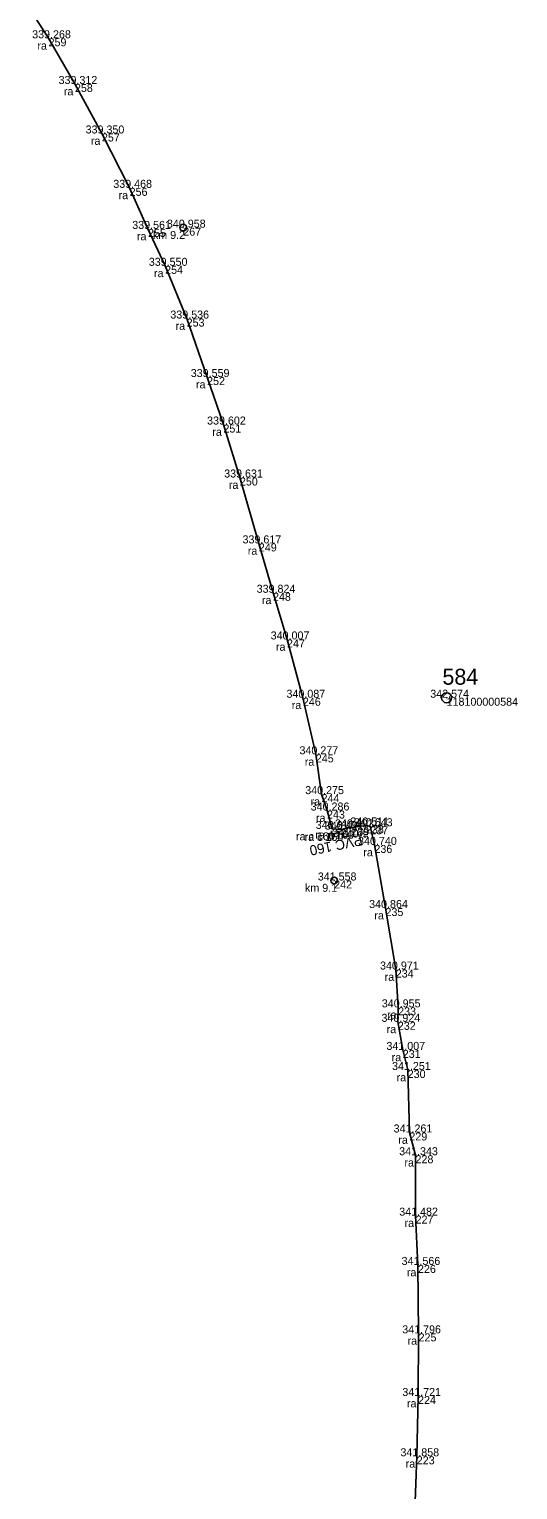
# Model space of a CAD drawing. Extents: x -727171 to -722443, y -945718 to -941834.
# Drawn here: x -725842.7 to -725769.5, y -942575.6 to -942356.6 of the extents above; entities that cross this region are included whole.
import ezdxf

# ---------------------------------------------------------------- set-up
doc = ezdxf.new("R2010")
doc.units = 0
for name, color, linetype in [('Vrstva 28', 7, 'Continuous'), ('Vrstva 35', 7, 'Continuous'), ('Vrstva 60', 7, 'Continuous'), ('Vrstva 61', 7, 'Continuous'), ('Vrstva 62', 7, 'Continuous'), ('Vrstva 63', 7, 'Continuous'), ('Vrstva 7', 7, 'Continuous')]:
    doc.layers.add(name, color=color, linetype=linetype)

msp = doc.modelspace()

# ---------------------------------------------------------------- linework, layer by layer
at = {"layer": 'Vrstva 28'}
msp.add_lwpolyline([(-725784.99, -942580.16), (-725784.63, -942570.61), (-725784.44, -942561.57), (-725784.36, -942552.18), (-725784.45, -942541.92), (-725784.81, -942534.53), (-725784.82, -942525.47), (-725785.74, -942522.06), (-725785.99, -942512.69), (-725786.73, -942509.68), (-725787.47, -942505.47), (-725787.42, -942503.3), (-725787.78, -942497.63), (-725789.32, -942488.41), (-725790.98, -942478.95), (-725791.61, -942476.15), (-725792.24, -942476.03), (-725794.44, -942476.32), (-725796.04, -942476.65), (-725797.33, -942476.55), (-725798.08, -942473.79), (-725798.9, -942471.33), (-725799.76, -942465.36), (-725801.7, -942456.88), (-725804.08, -942448.14), (-725806.18, -942441.14), (-725808.3, -942433.74), (-725811.14, -942423.86), (-725813.61, -942415.92), (-725816.06, -942408.8), (-725819.12, -942400.03), (-725822.35, -942392.12), (-725824.92, -942386.59), (-725827.67, -942380.43), (-725831.82, -942372.28), (-725835.87, -942364.86), (-725839.82, -942358.01), (-725842.72, -942353.5)], dxfattribs=at)
at = {"layer": 'Vrstva 35'}
msp.add_lwpolyline([(-725792.24, -942476.03), (-725794.44, -942476.32), (-725796.04, -942476.65), (-725797.33, -942476.55)], dxfattribs=at)
at = {"layer": 'Vrstva 60'}
for p, q in [((-725839.82, -942358.01), (-725839.82, -942358.01)), ((-725835.87, -942364.86), (-725835.87, -942364.86)), ((-725831.82, -942372.28), (-725831.82, -942372.28)), ((-725827.67, -942380.43), (-725827.67, -942380.43)), ((-725824.92, -942386.59), (-725824.92, -942386.59)), ((-725819.63, -942386.4), (-725819.63, -942386.4)), ((-725822.35, -942392.12), (-725822.35, -942392.12)), ((-725819.12, -942400.03), (-725819.12, -942400.03)), ((-725816.06, -942408.8), (-725816.06, -942408.8)), ((-725813.61, -942415.92), (-725813.61, -942415.92)), ((-725811.14, -942423.86), (-725811.14, -942423.86)), ((-725808.3, -942433.74), (-725808.3, -942433.74)), ((-725806.18, -942441.14), (-725806.18, -942441.14)), ((-725804.08, -942448.14), (-725804.08, -942448.14)), ((-725801.7, -942456.88), (-725801.7, -942456.88)), ((-725780.16, -942456.88), (-725780.16, -942456.88)), ((-725799.76, -942465.36), (-725799.76, -942465.36)), ((-725798.9, -942471.33), (-725798.9, -942471.33)), ((-725798.08, -942473.79), (-725798.08, -942473.79)), ((-725797.33, -942476.55), (-725797.33, -942476.55)), ((-725796.04, -942476.65), (-725796.04, -942476.65)), ((-725794.44, -942476.32), (-725794.44, -942476.32)), ((-725792.24, -942476.03), (-725792.24, -942476.03)), ((-725791.61, -942476.15), (-725791.61, -942476.15)), ((-725790.98, -942478.95), (-725790.98, -942478.95)), ((-725797.01, -942484.28), (-725797.01, -942484.28)), ((-725789.32, -942488.41), (-725789.32, -942488.41)), ((-725787.78, -942497.63), (-725787.78, -942497.63)), ((-725787.42, -942503.3), (-725787.42, -942503.3)), ((-725787.47, -942505.47), (-725787.47, -942505.47)), ((-725786.73, -942509.68), (-725786.73, -942509.68)), ((-725785.99, -942512.69), (-725785.99, -942512.69)), ((-725785.74, -942522.06), (-725785.74, -942522.06)), ((-725784.82, -942525.47), (-725784.82, -942525.47)), ((-725784.81, -942534.53), (-725784.81, -942534.53)), ((-725784.45, -942541.92), (-725784.45, -942541.92)), ((-725784.36, -942552.18), (-725784.36, -942552.18)), ((-725784.44, -942561.57), (-725784.44, -942561.57)), ((-725784.63, -942570.61), (-725784.63, -942570.61))]:
    msp.add_line(p, q, dxfattribs=at)
at = {"layer": 'Vrstva 63'}
msp.add_line((-725780.2, -942456.88), (-725780.1, -942456.88), dxfattribs=at)
msp.add_circle((-725780.16, -942456.88), 0.756, dxfattribs=at)
at = {"layer": 'Vrstva 7'}
for p, q in [((-725819.68, -942386.4), (-725819.58, -942386.4)), ((-725797.06, -942484.28), (-725796.96, -942484.28))]:
    msp.add_line(p, q, dxfattribs=at)
for centre in [(-725819.63, -942386.4), (-725797.01, -942484.28)]:
    msp.add_circle(centre, 0.5, dxfattribs=at)

# ---------------------------------------------------------------- texts
at = {"layer": 'Vrstva 35'}
msp.add_text('PVC 160', height=1.5, rotation=191.4815, dxfattribs=at).set_placement((-725792.94, -942477.5))
at = {"layer": 'Vrstva 60'}
for s, p in [('259', (-725839.82, -942359.21)), ('258', (-725835.87, -942366.06)), ('257', (-725831.82, -942373.48)), ('256', (-725827.67, -942381.63)), ('255', (-725824.92, -942387.79)), ('267', (-725819.63, -942387.6)), ('254', (-725822.35, -942393.32)), ('253', (-725819.12, -942401.23)), ('252', (-725816.06, -942410)), ('251', (-725813.61, -942417.12)), ('250', (-725811.14, -942425.06)), ('249', (-725808.3, -942434.94)), ('248', (-725806.18, -942442.34)), ('247', (-725804.08, -942449.34)), ('246', (-725801.7, -942458.08)), ('118100000584', (-725780.16, -942458.08)), ('245', (-725799.76, -942466.57)), ('244', (-725798.9, -942472.53)), ('243', (-725798.08, -942474.99)), ('241', (-725797.33, -942477.75)), ('240', (-725796.04, -942477.85)), ('239', (-725794.44, -942477.52)), ('238', (-725792.24, -942477.23)), ('237', (-725791.61, -942477.35)), ('236', (-725790.98, -942480.15)), ('242', (-725797.01, -942485.48)), ('235', (-725789.32, -942489.61)), ('234', (-725787.78, -942498.83)), ('233', (-725787.42, -942504.5)), ('232', (-725787.47, -942506.67)), ('231', (-725786.73, -942510.88)), ('230', (-725785.99, -942513.89)), ('229', (-725785.74, -942523.26)), ('228', (-725784.82, -942526.67)), ('227', (-725784.81, -942535.72)), ('226', (-725784.45, -942543.12)), ('225', (-725784.36, -942553.38)), ('224', (-725784.44, -942562.77)), ('223', (-725784.63, -942571.81))]:
    msp.add_text(s, height=1.2, dxfattribs=at).set_placement(p)
at = {"layer": 'Vrstva 61'}
for s, p in [('339.268', (-725842.28, -942358.01)), ('339.312', (-725838.32, -942364.86)), ('339.350', (-725834.27, -942372.28)), ('339.468', (-725830.12, -942380.43)), ('340.958', (-725822.08, -942386.4)), ('339.561', (-725827.28, -942386.59)), ('339.550', (-725824.8, -942392.12)), ('339.536', (-725821.57, -942400.03)), ('339.559', (-725818.51, -942408.8)), ('339.602', (-725816.06, -942415.92)), ('339.631', (-725813.5, -942423.86)), ('339.617', (-725810.75, -942433.74)), ('339.824', (-725808.63, -942441.14)), ('340.007', (-725806.53, -942448.14)), ('340.087', (-725804.16, -942456.88)), ('342.574', (-725782.61, -942456.88)), ('340.277', (-725802.21, -942465.36)), ('340.275', (-725801.35, -942471.33)), ('340.286', (-725800.53, -942473.79)), ('340.511', (-725794.59, -942476.03)), ('340.643', (-725794.06, -942476.15)), ('340.617', (-725799.78, -942476.55)), ('340.421', (-725798.4, -942476.65)), ('340.493', (-725796.89, -942476.32)), ('340.740', (-725793.43, -942478.95)), ('341.558', (-725799.47, -942484.28)), ('340.864', (-725791.77, -942488.41)), ('340.971', (-725790.14, -942497.63)), ('340.955', (-725789.87, -942503.3)), ('340.924', (-725789.92, -942505.47)), ('341.007', (-725789.18, -942509.68)), ('341.251', (-725788.34, -942512.69)), ('341.261', (-725788.1, -942522.06)), ('341.343', (-725787.27, -942525.47)), ('341.482', (-725787.26, -942534.53)), ('341.566', (-725786.91, -942541.92)), ('341.796', (-725786.81, -942552.18)), ('341.721', (-725786.8, -942561.57)), ('341.858', (-725787.08, -942570.61))]:
    msp.add_text(s, height=1.2, dxfattribs=at).set_placement(p)
at = {"layer": 'Vrstva 62'}
for s, p in [('ra', (-725841.49, -942359.71)), ('ra', (-725837.53, -942366.56)), ('ra', (-725833.48, -942373.98)), ('ra', (-725829.33, -942382.13)), ('ra', (-725826.58, -942388.29)), ('km 9.2', (-725824.18, -942388.1)), ('ra', (-725824.01, -942393.82)), ('ra', (-725820.78, -942401.73)), ('ra', (-725817.72, -942410.5)), ('ra', (-725815.27, -942417.62)), ('ra', (-725812.8, -942425.56)), ('ra', (-725809.96, -942435.44)), ('ra', (-725807.85, -942442.84)), ('ra', (-725805.74, -942449.84)), ('ra', (-725803.37, -942458.58)), ('ra', (-725801.42, -942467.07)), ('ra', (-725800.56, -942473.03)), ('ra', (-725799.74, -942475.49)), ('ra c 160', (-725802.73, -942478.25)), ('ra c 160', (-725801.44, -942478.35)), ('ra c 160', (-725799.84, -942478.02)), ('ra c 160', (-725797.64, -942477.73)), ('ra', (-725793.27, -942477.85)), ('ra', (-725792.64, -942480.65)), ('km 9.1', (-725801.39, -942485.98)), ('ra', (-725790.98, -942490.11)), ('ra', (-725789.44, -942499.33)), ('ra', (-725789.08, -942505)), ('ra', (-725789.14, -942507.17)), ('ra', (-725788.39, -942511.38)), ('ra', (-725787.65, -942514.39)), ('ra', (-725787.4, -942523.76)), ('ra', (-725786.48, -942527.17)), ('ra', (-725786.47, -942536.22)), ('ra', (-725786.12, -942543.62)), ('ra', (-725786.02, -942553.88)), ('ra', (-725786.1, -942563.27)), ('ra', (-725786.29, -942572.31))]:
    msp.add_text(s, height=1.2, dxfattribs=at).set_placement(p)
at = {"layer": 'Vrstva 63'}
msp.add_text('584', height=2.4, dxfattribs=at).set_placement((-725780.78, -942454.93))

doc.saveas('drawing.dxf')
